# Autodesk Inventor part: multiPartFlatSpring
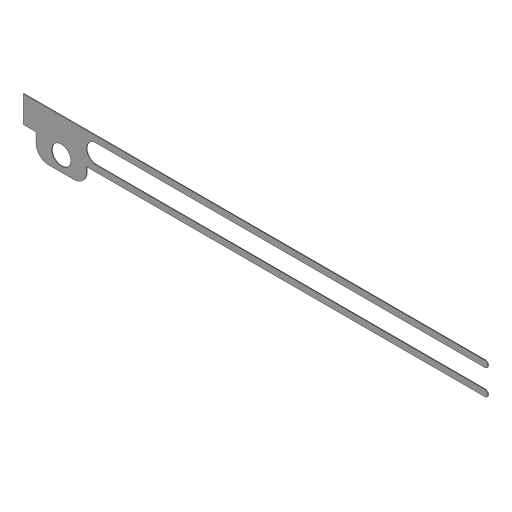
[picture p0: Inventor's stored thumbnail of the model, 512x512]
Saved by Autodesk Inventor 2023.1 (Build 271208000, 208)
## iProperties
Created: 2022-02
Part Number: multiPartFlatSpring
Material: Stainless Steel
Document SubType Name: Sheet Metal
Designer: Fabian Trauzettel
Density: 8 g/cm^3
Sheet Metal Rule: Default_mm
Appearance: Semi-Polished
Flat Pattern Width: 0.775653 cm
Flat Pattern Length: 7.35 cm
Flat Pattern Area: 5.70105 cm^2
Sheet Metal Width: 7.757 mm
Sheet Metal Length: 73.500 mm
Sheet Metal Area: 570.105 mm^2
Author: Fabian Trauzettel
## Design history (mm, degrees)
node "Face1"
  sketch "Sketch1"
    geometry: L1 (0, 0)-(63.5, 0); L2 (63.5, 0)-(63.5, 5); L3 (63.5, 5)-(0, 5); L4 (0, 5)-(0, 0); L5 (-8, 0.782)-(-10, 0.782) reference; L6 (-8, -3.257)-(-8, 0.782) reference; L7 (0, -3.257)-(-8, -3.257) reference; L8 (0, 3.932)-(0, -3.257) reference; L9 (-0.953, 3.932)-(0, 3.932) reference; L10 (-0.953, -1.068)-(-0.953, 3.932) reference; L11 (-1.547, -1.068)-(-0.953, -1.068) reference; L12 (-1.547, 3.932)-(-1.547, -1.068) reference; L13 (-2.5, 3.932)-(-1.547, 3.932) reference; L14 (-2.5, 5.812)-(-2.5, 3.932) reference; L15 (-10, 5.812)-(-2.5, 5.812) reference; L16 (-10, 5.812)-(-10, 0.782) reference; L17 (0, 0)-(0, -3.257); L18 (0, -3.257)-(-8, -3.257); L19 (-8, 0.782)-(-8, -3.257); L20 (-8, 0.782)-(-10, 0.782); L21 (-10, 0.782)-(-10, 5.812); L22 (-10, 5.812)-(0, 5.812); L23 (0, 5.812)-(0, 5)
    constraints: 22 end point, 6 equal length, 3 perpendicular, 2 point on line, 1 horizontal
    dimensions: "d0" = 63.5 distance of L3.end L2.end; "d1" = 5 distance of L2.end L1.end
pattern_linear "Rectangular Pattern1" dims "d5" = 4.7
bend "Bend1" dims "d2" = 0.1 (= Thickness), "d6" = 0.1 (= BendReliefWidth), "d7" = 0.05 (= BendReliefDepth), "d8" = 0.2 (= MinimumRemnant), "d9" = 0.1 (= TransitionRadius), "d10" = 0.1 (= BendRadius), "SeamGap" = 0.01
sketch "Sketch2"
  geometry: C1 r 1.7 at (4, -0.412) reference
extrude "Extrusion2" cut sketch "Sketch2" extent not by distance; stored distance "d13" = 0; taper "d14" = 0 deg
sketch "Sketch3"
  geometry: L1 (0, 5)-(-10, 5); L2 (-10, 0.782)-(-10, 5.812) reference; L3 (0, 5.812)-(-10, 5.812) reference; L4 (-10, 5.812)-(0, 5.812); L5 (-10, 5)-(-10, 5.812); L6 (-10, 5.812)-(0, 5.812) reference; L7 (0, 5.812)-(0, 5); 1 further point
  constraints: 8 end point, 2 collinear, 1 horizontal, 1 perpendicular, 1 point on line
extrude "Extrusion3" cut sketch "Sketch3" extent not by distance; stored distance "d15" = 0; taper "d16" = 0 deg
sketch "Sketch4"
  geometry: L1 (0, -3.257)-(0, 0) reference; L2 (0, -3.257)-(-8, -3.257) reference; L3 (-8, 0.782)-(-8, -3.257) reference; L4 (-8, -3.257)-(0, -3.257) reference; L5 (-8, -2.757)-(0, -2.757); L6 (0, -2.757)-(0, -3.257); L7 (0, -3.257)-(-8, -3.257); L8 (-8, -3.257)-(-8, -2.757)
  constraints: 8 end point, 2 parallel, 1 horizontal, 1 perpendicular, 1 point on line
  dimensions: "d18" = 0.5 distance between parallel lines of L2 L5
extrude "Extrusion4" cut sketch "Sketch4" distance "d19" = 10; taper "d20" = 0 deg
feature "Corner Round1" dims "d21" = 2
sketch "Sketch5"
  geometry: C1 r 1.7 at (-4, -0.412) reference; C2 r 1.5 at (-4, -0.412); 1 further point
  constraints: 1 centre point, 1 coincident
  dimensions: "d22" = 3 diameter of C2
extrude "Extrusion5" join sketch "Sketch5" stored distance "d23" = 10; taper "d24" = 0 deg
pattern_linear "Rectangular Pattern2" dims "d27" = 4.7
sketch "Sketch6"
  geometry: L1 (63.5, 5)-(63.5, 0) reference; L2 (63.5, 2.5)-(1.5, 2.5); L3 (63.5, 1)-(1.5, 1); L4 (1.5, 4)-(63.5, 4); L5 (0, 0)-(63.5, 0) reference; L6 (0, 0)-(0, 5); L7 (-10, 5)-(63.5, 5) reference; A1 r 1.5 centre (63.5, 2.5) between (63.5, 1) and (63.5, 4); A2 r 1.5 centre (1.5, 2.5) between (1.5, 4) and (1.5, 1); 1 further point
  constraints: 10 end point, 5 tangent, 4 point on circle, 2 centre point, 2 midpoint, 1 parallel, 1 perpendicular, 1 point on line, 1 vertical
  dimensions: "d28" = 1 distance between parallel lines of L7 L4
extrude "Extrusion6" cut sketch "Sketch6" extent not by distance; stored distance "d29" = 10; taper "d30" = 0 deg
fillet "Fillet1" dims "d31" = 0.5
split "Split1"
body "Solid1"
face "Plate1" dims "d2" = 0.1 (= Thickness)
node "Reference1"
node "Reference3"
feature "Definition1"
other parameters: "Thickness" = 0.1 (derived), "BendRadius" = 0.1 (= Thickness), "BendReliefWidth" = 0.1 (= Thickness), "BendReliefDepth" = 0.05 (= 0.5 x Thickness), "CornerReliefSize" = 0.4 (= 4 x Thickness), "MinimumRemnant" = 0.2 (= 2 x Thickness), "TransitionRadius" = 0.1 (= BendRadius), "JacobiRadiusSize" = 0.1 (= BendRadius), "GapSize" = 0.1 (= Thickness), "BendRadius" = 0.1, "BendReliefDepth" = 0.05, "BendReliefWidth" = 0.1, "CornerReliefSize" = 0.4, "GapSize" = 0.1, "JacobiRadiusSize" = 0.1, "MinimumRemnant" = 0.2, "Thickness" = 0.1, "TransitionRadius" = 0.1
